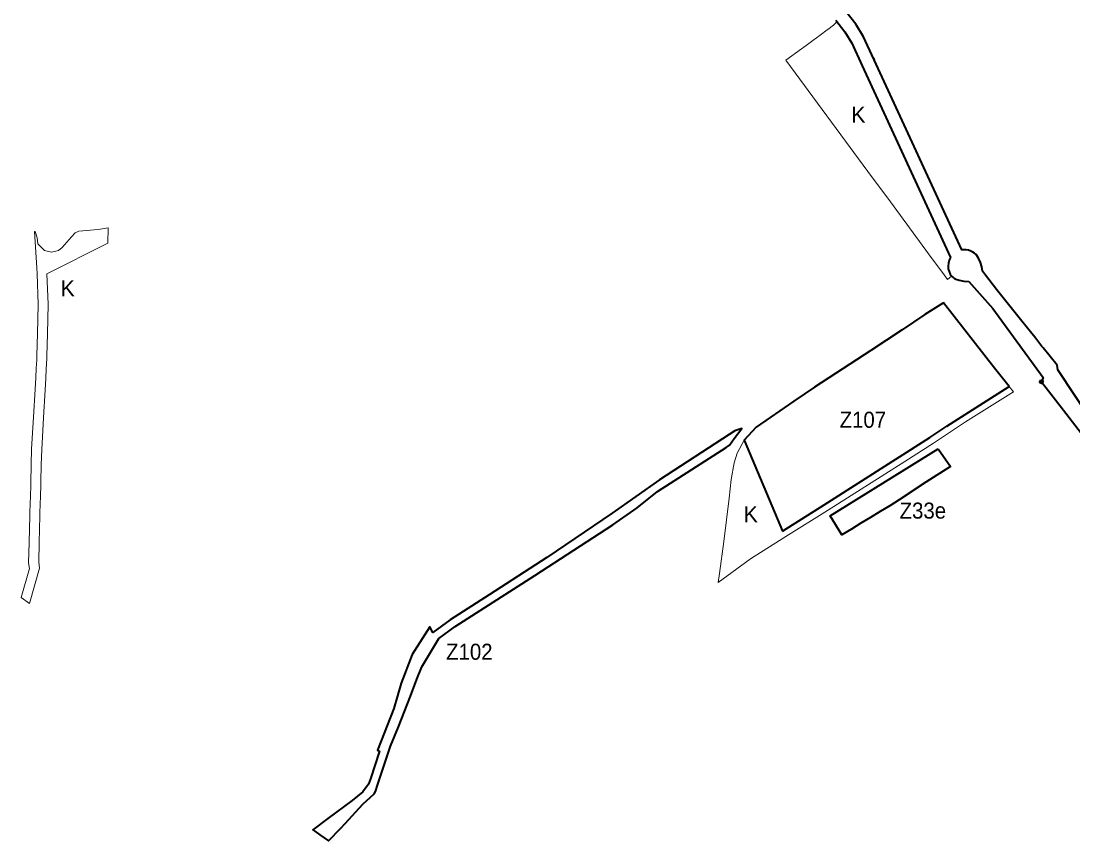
# Model space of a CAD drawing. Extents: x -650276 to -642489, y -1074311 to -1066658.
# Drawn here: x -649001 to -647428, y -1072846 to -1071620 of the extents above; entities that cross this region are included whole.
import ezdxf

# ---------------------------------------------------------------- set-up
doc = ezdxf.new("R2010")
doc.units = 0
doc.header["$LTSCALE"] = 9.6
doc.header["$PDMODE"] = 32
doc.header["$PDSIZE"] = 4.8
for name, color, linetype, lineweight in [('44', 7, 'Continuous', 40), ('45', 7, 'Continuous', 40), ('46', 7, 'Continuous', 13), ('47', 7, 'Continuous', 13), ('48', 7, 'Continuous', 35)]:
    doc.layers.add(name, color=color, linetype=linetype, lineweight=lineweight)

msp = doc.modelspace()

# ---------------------------------------------------------------- linework, layer by layer
at = {"layer": '44'}
for points in [[(-647725.629, -1071678.373), (-647735.352, -1071657.117), (-647741.34, -1071644.028), (-647753.065, -1071625.201), (-647767.784, -1071606.225), (-647782.408, -1071590.847), (-647798.911, -1071576.526), (-647817.375, -1071563.458), (-647834.953, -1071553.406)], [(-647782.97, -1071619.278), (-647769.498, -1071636.647), (-647758.994, -1071653.513), (-647743.48, -1071687.426), (-647611.514, -1071974.086)], [(-647563.77, -1071994.38), (-647564.751, -1071987.939), (-647566.62, -1071981.3), (-647569.422, -1071974.943), (-647573.283, -1071969.627), (-647575.415, -1071967.709), (-647577.881, -1071965.979), (-647581.036, -1071964.346), (-647584.363, -1071963.196), (-647588.064, -1071962.51), (-647591.518, -1071962.387), (-647594.731, -1071962.714), (-647725.614, -1071678.405), (-647726.774, -1071675.885), (-647725.629, -1071678.373)], [(-647611.514, -1071974.086), (-647613.455, -1071978.031), (-647614.654, -1071982.238), (-647615.083, -1071986.65), (-647614.76, -1071990.762), (-647613.637, -1071995.081), (-647611.779, -1071999.069), (-647609.808, -1072001.962)], [(-647542.57, -1072021.99), (-647558.97, -1072000.62), (-647563.77, -1071994.38)], [(-647609.808, -1072001.962), (-647604.924, -1072005.628), (-647598.384, -1072007.852), (-647591.564, -1072009.255), (-647584.202, -1072009.747)], [(-647584.202, -1072009.747), (-647547.916, -1072050.439), (-647473.022, -1072153.375), (-647475.57, -1072159.74)], [(-647452.23, -1072134.91), (-647472.86, -1072109.13), (-647474.72, -1072106.81), (-647485.6, -1072093.2), (-647504.73, -1072069.29), (-647542.57, -1072021.99)], [(-647376.68, -1072222.29), (-647401.221, -1072217.342), (-647451.21, -1072142.08), (-647452.23, -1072134.91)], [(-647475.57, -1072159.74), (-647447.73, -1072195.72), (-647407.34, -1072247.93)]]:
    msp.add_lwpolyline(points, dxfattribs=at)
msp.add_lwpolyline([(-648049.33, -1072323.77), (-647946.88, -1072257.82), (-647941.77, -1072254.45), (-647934.9, -1072244.55), (-647923.16, -1072229.85), (-647933.95, -1072233.18), (-647942.21, -1072238.54), (-648046.69, -1072306.3), (-648117.12, -1072356), (-648214.73, -1072422.41), (-648300.98, -1072478.1), (-648359.61, -1072515.85), (-648385.28, -1072534.41), (-648389.69, -1072526.36), (-648416.41, -1072567.43), (-648432.45, -1072610.56), (-648443.77, -1072648.02), (-648468.01, -1072710.44), (-648465.25, -1072712.03), (-648478.58, -1072753.49), (-648481.62, -1072761.39), (-648489.76, -1072772.74), (-648506.1, -1072785.56), (-648542.43, -1072812.6), (-648564.86, -1072829.45), (-648561.69, -1072831.54), (-648554.22, -1072836.89), (-648541.102, -1072846.281), (-648522.66, -1072826.92), (-648516.44, -1072820.39), (-648489.69, -1072791.37), (-648473.13, -1072775.58), (-648470.89, -1072772.42), (-648467.286, -1072761.426), (-648448.58, -1072704.37), (-648436.75, -1072675.79), (-648418.45, -1072629.91), (-648409.08, -1072604.25), (-648401.91, -1072586.1), (-648376.47, -1072543.52), (-648351.83, -1072525.81), (-648232.86, -1072449.45), (-648116.32, -1072373.44), (-648079.76, -1072348.46)], close=True, dxfattribs=at)
msp.add_point((-647475.57, -1072159.74), dxfattribs=at)
at = {"layer": '45'}
for points in [[(-647621.97, -1072041.73), (-647649.76, -1072059.06), (-647683.63, -1072081.94), (-647730.53, -1072112.84), (-647814.58, -1072167.67), (-647845.58, -1072188.94), (-647901.91, -1072227.6), (-647919.68, -1072247.09), (-647862.615, -1072383.084)], [(-647523.71, -1072167.071), (-647545.44, -1072139.35), (-647621.97, -1072041.73)], [(-647862.615, -1072383.084), (-647800.2, -1072343.615), (-647642.504, -1072242.974), (-647616.719, -1072226.154), (-647523.71, -1072167.071)]]:
    msp.add_lwpolyline(points, dxfattribs=at)
msp.add_lwpolyline([(-647629.67, -1072259.82), (-647611.51, -1072286.26), (-647648.09, -1072309.95), (-647688.26, -1072336.06), (-647702.35, -1072345.14), (-647716.62, -1072353.95), (-647730.97, -1072362.6), (-647745.32, -1072371.26), (-647759.68, -1072379.91), (-647774.04, -1072388.57), (-647791.198, -1072360.119)], close=True, dxfattribs=at)
at = {"layer": '47'}
for points in [[(-647817.33, -1071649.51), (-647806.35, -1071641.47), (-647795.76, -1071633.72), (-647794.98, -1071633.15), (-647786.1, -1071626.65), (-647781.134, -1071621.645), (-647769.498, -1071636.647), (-647758.889, -1071653.742), (-647743.48, -1071687.426), (-647611.514, -1071974.086), (-647613.455, -1071978.031), (-647614.654, -1071982.238), (-647615.083, -1071986.65), (-647614.76, -1071990.762), (-647613.637, -1071995.081), (-647611.779, -1071999.069), (-647609.808, -1072001.962), (-647616.12, -1072006.7), (-647621.06, -1072000), (-647644.38, -1071968.3), (-647705.291, -1071885.501), (-647727.85, -1071854.86), (-647857.52, -1071678.92), (-647834.345, -1071661.969), (-647827.42, -1071656.89)], [(-648988.248, -1072491.089), (-648973.238, -1072438.27), (-648974.424, -1072429.462), (-648973.655, -1072400.254), (-648972.605, -1072360.164), (-648972.025, -1072338.183), (-648971.955, -1072335.341), (-648970.605, -1072283.823), (-648970.001, -1072260.788), (-648967.285, -1072213.663), (-648964.865, -1072171.684), (-648963.895, -1072154.905), (-648963.052, -1072140.301), (-648962.27, -1072125.223), (-648962.165, -1072120.949), (-648961.355, -1072088.12), (-648960.263, -1072043.893), (-648962.195, -1071998.309), (-648871.27, -1071952.643), (-648870.458, -1071929.441), (-648885.56, -1071932.1), (-648914.45, -1071934.78), (-648919.79, -1071937.27), (-648925.64, -1071943.18), (-648939.51, -1071959.25), (-648944.69, -1071963.44), (-648955.25, -1071966.15), (-648966.01, -1071963.74), (-648975.65, -1071953.47), (-648976.85, -1071944.78), (-648979.85, -1071935.11), (-648980.94, -1071935.12), (-648977.48, -1071989.2), (-648976.91, -1071998.2), (-648975.27, -1072044.01), (-648976.35, -1072087.75), (-648977.16, -1072120.58), (-648977.26, -1072124.65), (-648977.3, -1072126.08), (-648977.33, -1072127.34), (-648978.03, -1072139.48), (-648978.87, -1072154.04), (-648979.84, -1072170.82), (-648982.26, -1072212.8), (-648984.99, -1072260.16), (-648985.6, -1072283.43), (-648986.31, -1072310.66), (-648986.95, -1072334.96), (-648987.02, -1072337.8), (-648987.6, -1072359.77), (-648988.65, -1072399.86), (-648989.45, -1072430.27), (-648988.27, -1072439.04), (-649000.851, -1072482.138)]]:
    msp.add_lwpolyline(points, close=True, dxfattribs=at)
for points in [[(-647795.4, -1072352.415), (-647679.66, -1072279.15), (-647637.082, -1072251.377), (-647611.306, -1072234.563), (-647589.02, -1072219.66), (-647517.51, -1072174.98), (-647523.71, -1072167.071), (-647616.719, -1072226.154), (-647642.504, -1072242.974), (-647800.888, -1072344.051), (-647810.794, -1072350.315), (-647862.615, -1072383.084), (-647919.68, -1072247.09)], [(-647919.68, -1072247.09), (-647930.36, -1072266.38), (-647934.86, -1072280.99), (-647939.26, -1072306.1), (-647942.54, -1072333.82), (-647950.2, -1072398.61), (-647956.786, -1072446.511)], [(-647956.786, -1072446.511), (-647958.82, -1072459.74), (-647910.27, -1072424.51), (-647857.52, -1072391.14), (-647795.4, -1072352.415)]]:
    msp.add_lwpolyline(points, dxfattribs=at)

# ---------------------------------------------------------------- texts
at = {"layer": '44', "width": 0.95}
msp.add_text('Z102', height=24, dxfattribs=at).set_placement((-648365.47, -1072575.389))
msp.add_text('Z102', height=24, dxfattribs=at).set_placement((-648365.47, -1072575.389))
at = {"layer": '46', "width": 0.95}
for s, p in [('Z107', (-647777.22, -1072228.544)), ('Z33e', (-647687.519, -1072364.366))]:
    msp.add_text(s, height=24, dxfattribs=at).set_placement(p)
at = {"layer": '48'}
for p in [(-647759.879, -1071772.452), (-647759.879, -1071772.452), (-648941.849, -1072032.089), (-648941.849, -1072032.089), (-647920.872, -1072369.761)]:
    msp.add_text('K', height=24, dxfattribs=at).set_placement(p)

doc.saveas('drawing.dxf')
